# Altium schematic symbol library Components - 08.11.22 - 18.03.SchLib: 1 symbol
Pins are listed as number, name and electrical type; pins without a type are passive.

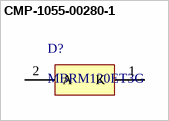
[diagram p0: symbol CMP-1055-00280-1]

## CMP-1055-00280-1
designator D?, comment MBRM120ET3G
Schottky Power Rectifier, 2-Pin Powermite, Pb-Free, Tape and Reel; Manufacturer: On Semiconductor; Configuration: Single; IFSM Max (A): 50
footprint ONSC-POWERMITE-2-457-04_D_V (POWERMITE, 2-Leads, Body 1.965x1.9mm)
pins: 1 K, 2 A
